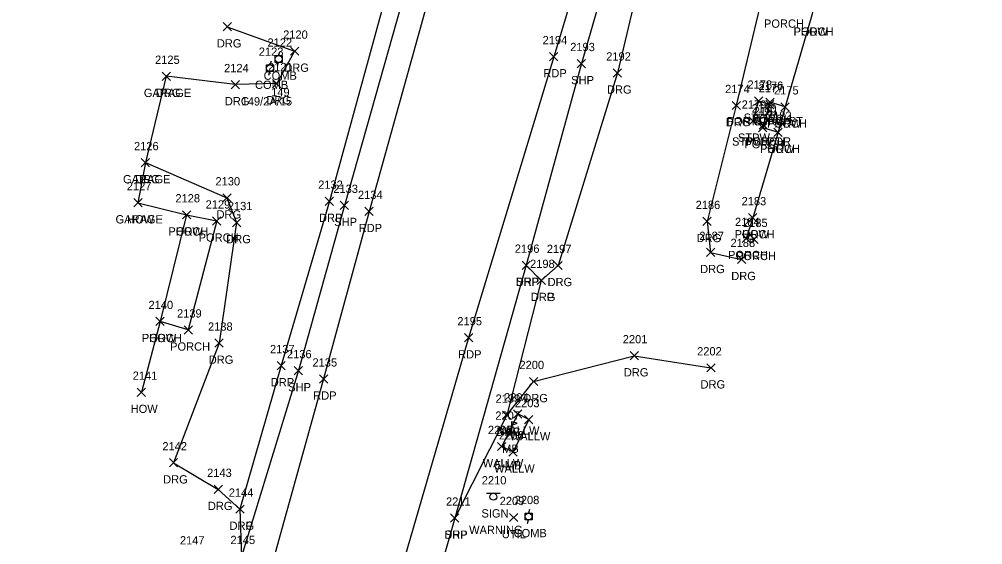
# Model space of a CAD drawing. Extents: x 1443071 to 1445292, y 614024 to 622563.
# Drawn here: x 1444521.8 to 1444754.4, y 622066 to 622193 of the extents above; entities that cross this region are included whole.
import ezdxf

# ---------------------------------------------------------------- set-up
doc = ezdxf.new("R2010")
doc.units = 0
for name, color, linetype in [('L_A', 7, 'Continuous'), ('L_C', 7, 'Continuous'), ('L_I', 7, 'Continuous'), ('L_TIC', 7, 'Continuous'), ('LBC', 7, 'Continuous'), ('LBF', 7, 'Continuous'), ('LMB', 7, 'Continuous'), ('LW', 7, 'Continuous'), ('P_A', 7, 'Continuous'), ('P_I', 7, 'Continuous'), ('P_TIC', 7, 'Continuous'), ('PET', 7, 'Continuous'), ('PSP', 7, 'Continuous'), ('R_A', 7, 'Continuous'), ('R_I', 7, 'Continuous'), ('R_TIC', 7, 'Continuous'), ('RDG', 7, 'Continuous'), ('RDP', 7, 'Continuous'), ('S_A', 7, 'Continuous'), ('S_C', 7, 'Continuous'), ('S_I', 7, 'Continuous'), ('SSGN', 7, 'Continuous'), ('U_A', 7, 'Continuous'), ('U_C', 7, 'Continuous'), ('U_I', 7, 'Continuous'), ('UDEFAULT', 7, 'Continuous'), ('UP', 7, 'Continuous')]:
    doc.layers.add(name, color=color, linetype=linetype)

msp = doc.modelspace()

# ---------------------------------------------------------------- linework, layer by layer
at = {"layer": 'L_TIC'}
for points in [[(1444556.27, 622178.18), (1444558.27, 622180.18)], [(1444558.27, 622178.18), (1444556.27, 622180.18)], [(1444699.32, 622172.18), (1444701.32, 622174.18)], [(1444701.32, 622172.18), (1444699.32, 622174.18)], [(1444702.03, 622171.33), (1444704.03, 622173.33)], [(1444704.03, 622171.33), (1444702.03, 622173.33)], [(1444702.03, 622171.33), (1444704.03, 622173.33)], [(1444704.03, 622171.33), (1444702.03, 622173.33)], [(1444702.04, 622171.91), (1444704.04, 622173.91)], [(1444704.04, 622171.91), (1444702.04, 622173.91)], [(1444705.72, 622170.79), (1444707.72, 622172.79)], [(1444707.72, 622170.79), (1444705.72, 622172.79)], [(1444705.72, 622170.79), (1444707.72, 622172.79)], [(1444707.72, 622170.79), (1444705.72, 622172.79)], [(1444697.93, 622167.36), (1444699.93, 622169.36)], [(1444699.93, 622167.36), (1444697.93, 622169.36)], [(1444700.27, 622165.77), (1444702.27, 622167.77)], [(1444702.27, 622165.77), (1444700.27, 622167.77)], [(1444700.44, 622166.43), (1444702.44, 622168.43)], [(1444702.44, 622166.43), (1444700.44, 622168.43)], [(1444700.44, 622166.43), (1444702.44, 622168.43)], [(1444702.44, 622166.43), (1444700.44, 622168.43)], [(1444704.02, 622164.67), (1444706.02, 622166.67)], [(1444706.02, 622164.67), (1444704.02, 622166.67)], [(1444704.02, 622164.67), (1444706.02, 622166.67)], [(1444706.02, 622164.67), (1444704.02, 622166.67)], [(1444551.25, 622157.32), (1444553.25, 622159.32)], [(1444553.25, 622157.32), (1444551.25, 622159.32)], [(1444549.44, 622147.62), (1444551.44, 622149.62)], [(1444551.44, 622147.62), (1444549.44, 622149.62)], [(1444549.44, 622147.62), (1444551.44, 622149.62)], [(1444551.44, 622147.62), (1444549.44, 622149.62)], [(1444561.18, 622144.71), (1444563.18, 622146.71)], [(1444563.18, 622144.71), (1444561.18, 622146.71)], [(1444561.18, 622144.71), (1444563.18, 622146.71)], [(1444563.18, 622144.71), (1444561.18, 622146.71)], [(1444568.49, 622143.22), (1444570.49, 622145.22)], [(1444570.49, 622143.22), (1444568.49, 622145.22)], [(1444697.9, 622144.01), (1444699.9, 622146.01)], [(1444699.9, 622144.01), (1444697.9, 622146.01)], [(1444697.9, 622144.01), (1444699.9, 622146.01)], [(1444699.9, 622144.01), (1444697.9, 622146.01)], [(1444696.31, 622139), (1444698.31, 622141)], [(1444698.31, 622139), (1444696.31, 622141)], [(1444698.24, 622138.77), (1444700.24, 622140.77)], [(1444700.24, 622138.77), (1444698.24, 622140.77)], [(1444554.78, 622118.94), (1444556.78, 622120.94)], [(1444556.78, 622118.94), (1444554.78, 622120.94)], [(1444554.78, 622118.94), (1444556.78, 622120.94)], [(1444556.78, 622118.94), (1444554.78, 622120.94)], [(1444561.59, 622116.89), (1444563.59, 622118.89)], [(1444563.59, 622116.89), (1444561.59, 622118.89)], [(1444550.3, 622101.84), (1444552.3, 622103.84)], [(1444552.3, 622101.84), (1444550.3, 622103.84)], [(1444641.17, 622096.61), (1444643.17, 622098.61)], [(1444643.17, 622096.61), (1444641.17, 622098.61)], [(1444643.8, 622095.22), (1444645.8, 622097.22)], [(1444645.8, 622095.22), (1444643.8, 622097.22)], [(1444643.8, 622095.22), (1444645.8, 622097.22)], [(1444645.8, 622095.22), (1444643.8, 622097.22)], [(1444637.28, 622088.73), (1444639.28, 622090.73)], [(1444639.28, 622088.73), (1444637.28, 622090.73)], [(1444640.02, 622087.42), (1444642.02, 622089.42)], [(1444642.02, 622087.42), (1444640.02, 622089.42)], [(1444640.02, 622087.42), (1444642.02, 622089.42)], [(1444642.02, 622087.42), (1444640.02, 622089.42)]]:
    msp.add_lwpolyline(points, dxfattribs=at)
at = {"layer": 'LBC'}
for points in [[(1444744.88, 622235.69), (1444725.69, 622241.03), (1444723.59, 622234.25), (1444722.14, 622228.45), (1444716.63, 622208.31), (1444713.14, 622193.99), (1444706.72, 622171.79), (1444705.02, 622165.67), (1444698.9, 622145.01)], [(1444557.27, 622179.18), (1444552.25, 622158.32), (1444550.44, 622148.62)], [(1444550.44, 622148.62), (1444562.18, 622145.71), (1444555.78, 622119.94), (1444551.3, 622102.84)]]:
    msp.add_lwpolyline(points, dxfattribs=at)
at = {"layer": 'LBF'}
for points in [[(1444703.03, 622172.33), (1444700.32, 622173.18), (1444698.93, 622168.36), (1444701.44, 622167.43)], [(1444706.72, 622171.79), (1444703.04, 622172.91), (1444703.03, 622172.33), (1444701.44, 622167.43), (1444701.27, 622166.77), (1444705.02, 622165.67)], [(1444562.18, 622145.71), (1444569.49, 622144.22), (1444562.59, 622117.89), (1444555.78, 622119.94)], [(1444698.9, 622145.01), (1444697.31, 622140), (1444699.24, 622139.77)]]:
    msp.add_lwpolyline(points, dxfattribs=at)
at = {"layer": 'LMB'}
for p, q in [((1444640.73, 622093.2), (1444640.73, 622095.8)), ((1444640.73, 622095.79), (1444642.02, 622095.41)), ((1444640.73, 622094.89), (1444642.02, 622095.4)), ((1444640.08, 622093.19), (1444640.08, 622093.19))]:
    msp.add_line(p, q, dxfattribs=at)
msp.add_circle((1444640.08, 622093.19), 0.656, dxfattribs=at)
at = {"layer": 'LW'}
for points in [[(1444644.8, 622096.22), (1444642.17, 622097.61), (1444638.28, 622089.73), (1444641.02, 622088.42)], [(1444644.8, 622096.22), (1444641.02, 622088.42)]]:
    msp.add_lwpolyline(points, dxfattribs=at)
at = {"layer": 'P_TIC'}
for points in [[(1444649.85, 622182.92), (1444651.85, 622184.92)], [(1444651.85, 622182.92), (1444649.85, 622184.92)], [(1444656.52, 622181.26), (1444658.52, 622183.26)], [(1444658.52, 622181.26), (1444656.52, 622183.26)], [(1444599.31, 622146.99), (1444601.31, 622148.99)], [(1444601.31, 622146.99), (1444599.31, 622148.99)], [(1444605.26, 622145.53), (1444607.26, 622147.53)], [(1444607.26, 622145.53), (1444605.26, 622147.53)], [(1444643.19, 622132.53), (1444645.19, 622134.53)], [(1444645.19, 622132.53), (1444643.19, 622134.53)], [(1444629.28, 622115), (1444631.28, 622117)], [(1444631.28, 622115), (1444629.28, 622117)], [(1444588.19, 622107.06), (1444590.19, 622109.06)], [(1444590.19, 622107.06), (1444588.19, 622109.06)], [(1444594.29, 622105.04), (1444596.29, 622107.04)], [(1444596.29, 622105.04), (1444594.29, 622107.04)], [(1444625.95, 622071.43), (1444627.95, 622073.43)], [(1444627.95, 622071.43), (1444625.95, 622073.43)]]:
    msp.add_lwpolyline(points, dxfattribs=at)
at = {"layer": 'PET'}
for points in [[(1444754.44, 622544.13), (1444741.07, 622497.37), (1444724.21, 622436.63), (1444710.62, 622388.87), (1444697.45, 622342.15), (1444675, 622264.13), (1444650.85, 622183.92), (1444630.28, 622116), (1444610.88, 622049.25), (1444594.96, 621996.24), (1444563.37, 621884.27), (1444533.4, 621779.05), (1444495.09, 621640.86), (1444437.04, 621433.18), (1444409.83, 621332.84), (1444393.99, 621275.61), (1444360.23, 621155.32)], [(1444707.59, 622509.11), (1444700.19, 622484.07), (1444679.05, 622409.28), (1444655.77, 622327.83), (1444650.07, 622306.66), (1444636.13, 622255.68), (1444623.55, 622208.8), (1444606.26, 622146.53), (1444595.29, 622106.04), (1444582.56, 622060.23), (1444534.43, 621893.79), (1444481.57, 621704.27), (1444439.29, 621553.82), (1444408.11, 621445.28), (1444395.03, 621397.39), (1444367.96, 621301.44), (1444350.41, 621238.76), (1444319.14, 621126.97)]]:
    msp.add_lwpolyline(points, dxfattribs=at)
at = {"layer": 'PSP'}
for points in [[(1444703.05, 622509.58), (1444696.35, 622485.04), (1444679.96, 622426.95), (1444670.67, 622398.4), (1444651.65, 622328.99), (1444645.77, 622309.01), (1444600.31, 622147.99), (1444589.19, 622108.06), (1444575.49, 622063.15), (1444529.28, 621895.39), (1444476.53, 621706.36), (1444455.46, 621630.82), (1444442.09, 621578.45), (1444424.77, 621519.75), (1444412.09, 621475.26), (1444390.88, 621397.93), (1444363.76, 621301.82), (1444345.99, 621239.2), (1444324.65, 621163.68)], [(1444745.15, 622495.54), (1444738.65, 622472.69), (1444728.21, 622436.2), (1444714.89, 622387.13), (1444701.45, 622339.69), (1444679.77, 622260.17), (1444671.12, 622229.57), (1444657.52, 622182.26), (1444644.19, 622133.53), (1444626.95, 622072.43), (1444608.5, 622007.83), (1444599.1, 621977.5), (1444572.99, 621881.76), (1444551.74, 621805.05), (1444541.41, 621769.53), (1444519.46, 621688.51), (1444505.68, 621638.77), (1444452.32, 621450.13), (1444441.68, 621411.27), (1444418.22, 621330.76), (1444405.98, 621283.95), (1444397.04, 621252.99), (1444383.69, 621203.04)]]:
    msp.add_lwpolyline(points, dxfattribs=at)
at = {"layer": 'R_TIC'}
for points in [[(1444571.01, 622190.14), (1444573.01, 622192.14)], [(1444573.01, 622190.14), (1444571.01, 622192.14)], [(1444587.29, 622184.26), (1444589.29, 622186.26)], [(1444589.29, 622184.26), (1444587.29, 622186.26)], [(1444556.27, 622178.18), (1444558.27, 622180.18)], [(1444558.27, 622178.18), (1444556.27, 622180.18)], [(1444665.21, 622178.99), (1444667.21, 622180.99)], [(1444667.21, 622178.99), (1444665.21, 622180.99)], [(1444572.95, 622176.17), (1444574.95, 622178.17)], [(1444574.95, 622176.17), (1444572.95, 622178.17)], [(1444582.97, 622176.42), (1444584.97, 622178.42)], [(1444584.97, 622176.42), (1444582.97, 622178.42)], [(1444693.93, 622171.12), (1444695.93, 622173.12)], [(1444695.93, 622171.12), (1444693.93, 622173.12)], [(1444551.25, 622157.32), (1444553.25, 622159.32)], [(1444553.25, 622157.32), (1444551.25, 622159.32)], [(1444570.94, 622148.81), (1444572.94, 622150.81)], [(1444572.94, 622148.81), (1444570.94, 622150.81)], [(1444595.67, 622147.99), (1444597.67, 622149.99)], [(1444597.67, 622147.99), (1444595.67, 622149.99)], [(1444573.28, 622142.84), (1444575.28, 622144.84)], [(1444575.28, 622142.84), (1444573.28, 622144.84)], [(1444686.86, 622143.11), (1444688.86, 622145.11)], [(1444688.86, 622143.11), (1444686.86, 622145.11)], [(1444687.71, 622135.62), (1444689.71, 622137.62)], [(1444689.71, 622135.62), (1444687.71, 622137.62)], [(1444695.22, 622133.93), (1444697.22, 622135.93)], [(1444697.22, 622133.93), (1444695.22, 622135.93)], [(1444643.19, 622132.53), (1444645.19, 622134.53)], [(1444645.19, 622132.53), (1444643.19, 622134.53)], [(1444650.88, 622132.47), (1444652.88, 622134.47)], [(1444652.88, 622132.47), (1444650.88, 622134.47)], [(1444646.82, 622128.87), (1444648.82, 622130.87)], [(1444648.82, 622128.87), (1444646.82, 622130.87)], [(1444646.82, 622128.87), (1444648.82, 622130.87)], [(1444648.82, 622128.87), (1444646.82, 622130.87)], [(1444569.05, 622113.71), (1444571.05, 622115.71)], [(1444571.05, 622113.71), (1444569.05, 622115.71)], [(1444669.29, 622110.66), (1444671.29, 622112.66)], [(1444671.29, 622110.66), (1444669.29, 622112.66)], [(1444584.03, 622108.27), (1444586.03, 622110.27)], [(1444586.03, 622108.27), (1444584.03, 622110.27)], [(1444687.81, 622107.74), (1444689.81, 622109.74)], [(1444689.81, 622107.74), (1444687.81, 622109.74)], [(1444645, 622104.43), (1444647, 622106.43)], [(1444647, 622104.43), (1444645, 622106.43)], [(1444638.5, 622096.3), (1444640.5, 622098.3)], [(1444640.5, 622096.3), (1444638.5, 622098.3)], [(1444638.5, 622096.3), (1444640.5, 622098.3)], [(1444640.5, 622096.3), (1444638.5, 622098.3)], [(1444558.04, 622084.79), (1444560.04, 622086.79)], [(1444560.04, 622084.79), (1444558.04, 622086.79)], [(1444568.84, 622078.37), (1444570.84, 622080.37)], [(1444570.84, 622078.37), (1444568.84, 622080.37)], [(1444574.08, 622073.59), (1444576.08, 622075.59)], [(1444576.08, 622073.59), (1444574.08, 622075.59)], [(1444574.08, 622073.59), (1444576.08, 622075.59)], [(1444576.08, 622073.59), (1444574.08, 622075.59)], [(1444625.95, 622071.43), (1444627.95, 622073.43)], [(1444627.95, 622071.43), (1444625.95, 622073.43)]]:
    msp.add_lwpolyline(points, dxfattribs=at)
at = {"layer": 'RDG'}
for points in [[(1444683.02, 622255.19), (1444696.87, 622250.43), (1444712.88, 622241.02), (1444711.87, 622227.43), (1444702.35, 622203.55), (1444694.93, 622172.12), (1444687.86, 622144.11), (1444688.71, 622136.62), (1444696.22, 622134.93)], [(1444674.55, 622230.15), (1444676.7, 622224.22), (1444666.21, 622179.99), (1444651.88, 622133.47), (1444647.82, 622129.87)], [(1444572.01, 622191.14), (1444588.29, 622185.26), (1444583.97, 622177.42), (1444573.95, 622177.17), (1444557.27, 622179.18)], [(1444552.25, 622158.32), (1444571.94, 622149.81), (1444574.28, 622143.84), (1444570.05, 622114.71), (1444559.04, 622085.79), (1444569.84, 622079.37), (1444575.08, 622074.59)], [(1444639.5, 622097.3), (1444646, 622105.43), (1444670.29, 622111.66), (1444688.81, 622108.74)]]:
    msp.add_lwpolyline(points, dxfattribs=at)
at = {"layer": 'RDP'}
for points in [[(1444645.77, 622309.01), (1444638.9, 622301.63), (1444626.44, 622256.61), (1444620.83, 622237.39), (1444614.71, 622214.93), (1444596.67, 622148.99), (1444585.03, 622109.27), (1444575.08, 622074.59), (1444575.49, 622063.15)], [(1444644.19, 622133.53), (1444647.82, 622129.87), (1444639.5, 622097.3), (1444626.95, 622072.43)]]:
    msp.add_lwpolyline(points, dxfattribs=at)
at = {"layer": 'SSGN'}
for p, q in [((1444634.62, 622078.43), (1444637.95, 622078.43)), ((1444636.27, 622077.59), (1444636.27, 622077.59))]:
    msp.add_line(p, q, dxfattribs=at)
msp.add_circle((1444636.27, 622077.59), 0.833, dxfattribs=at)
at = {"layer": 'UDEFAULT'}
for points in [[(1444640.15, 622071.57), (1444642.15, 622073.57)], [(1444642.15, 622071.57), (1444640.15, 622073.57)]]:
    msp.add_lwpolyline(points, dxfattribs=at)
at = {"layer": 'UP'}
for p, q in [((1444583.58, 622182.5), (1444583.58, 622184.17)), ((1444583.58, 622184.17), (1444585.24, 622184.17)), ((1444584.66, 622185), (1444584.41, 622184.17)), ((1444585.24, 622184.17), (1444585.24, 622182.5)), ((1444581.49, 622180.3), (1444581.49, 622181.96)), ((1444581.49, 622181.96), (1444583.16, 622181.96)), ((1444582.58, 622182.8), (1444582.33, 622181.96)), ((1444583.16, 622181.96), (1444583.16, 622180.3)), ((1444585.24, 622182.5), (1444583.58, 622182.5)), ((1444584.16, 622181.67), (1444584.41, 622182.5)), ((1444584.41, 622183.34), (1444584.41, 622183.34)), ((1444583.16, 622180.3), (1444581.49, 622180.3)), ((1444582.08, 622179.46), (1444582.33, 622180.3)), ((1444582.33, 622181.13), (1444582.33, 622181.13)), ((1444645.01, 622074.48), (1444644.76, 622073.65)), ((1444643.93, 622071.98), (1444643.93, 622073.65)), ((1444643.93, 622073.65), (1444645.6, 622073.65)), ((1444644.76, 622072.81), (1444644.76, 622072.81)), ((1444645.6, 622073.65), (1444645.6, 622071.98)), ((1444645.6, 622071.98), (1444643.93, 622071.98)), ((1444644.51, 622071.15), (1444644.76, 622071.98))]:
    msp.add_line(p, q, dxfattribs=at)
for centre in [(1444584.41, 622183.34), (1444582.33, 622181.13), (1444644.76, 622072.81)]:
    msp.add_circle(centre, 0.833, dxfattribs=at)

# ---------------------------------------------------------------- texts
at = {"layer": 'L_A'}
for s, p in [('PORCH', (1444701.61, 622190.91)), ('PORCH', (1444708.76, 622188.99)), ('HOW', (1444710.52, 622188.99)), ('GARAGE', (1444551.87, 622174.18)), ('STPW', (1444696.71, 622168.18)), ('PORCH', (1444698.66, 622167.91)), ('POR STPW ST', (1444692.61, 622167.33)), ('PORCH', (1444698.65, 622167.33)), ('PORCH', (1444702.34, 622166.79)), ('HOW', (1444704.11, 622166.79)), ('STPW', (1444695.32, 622163.36)), ('STPW POR', (1444693.89, 622162.43)), ('PORCH', (1444696.89, 622161.77)), ('PORCH', (1444697.06, 622162.43)), ('PORCH', (1444700.64, 622160.67)), ('HOW', (1444702.41, 622160.67)), ('GARAGE', (1444546.85, 622153.32)), ('GARAGE', (1444545.04, 622143.62)), ('HOW', (1444547.83, 622143.62)), ('PORCH', (1444557.8, 622140.71)), ('HOW', (1444559.57, 622140.71)), ('PORCH', (1444694.52, 622140.01)), ('HOW', (1444696.29, 622140.01)), ('PORCH', (1444565.11, 622139.22)), ('PORCH', (1444692.93, 622135)), ('PORCH', (1444694.86, 622134.77)), ('PORCH', (1444551.4, 622114.94)), ('HOW', (1444553.16, 622114.94)), ('PORCH', (1444558.21, 622112.89)), ('HOW', (1444548.69, 622097.84)), ('WALLW', (1444637.59, 622092.61)), ('WALLW', (1444640.22, 622091.22)), ('WALLW', (1444640.22, 622091.22)), ('MB', (1444638.39, 622088.19)), ('WALLW', (1444633.7, 622084.73)), ('WALLW', (1444636.44, 622083.42)), ('WALLW', (1444636.44, 622083.42))]:
    msp.add_text(s, height=2, dxfattribs=at).set_placement(p)
at = {"layer": 'L_C'}
msp.add_text('5-MB', height=2, dxfattribs=at).set_placement((1444636.67, 622084.19))
at = {"layer": 'L_I'}
for s, p in [('2125', (1444554.58, 622182.18)), ('2178', (1444697.62, 622176.18)), ('2176', (1444700.29, 622175.91)), ('2177', (1444700.34, 622175.33)), ('2177', (1444700.34, 622175.33)), ('2175', (1444704.03, 622174.79)), ('2175', (1444704.03, 622174.79)), ('2179', (1444696.23, 622171.36)), ('2180', (1444698.66, 622170.43)), ('2180', (1444698.66, 622170.43)), ('2181', (1444699.14, 622169.77)), ('2182', (1444702.33, 622168.67)), ('2182', (1444702.33, 622168.67)), ('2126', (1444549.5, 622161.32)), ('2127', (1444547.75, 622151.62)), ('2127', (1444547.75, 622151.62)), ('2128', (1444559.49, 622148.71)), ('2128', (1444559.49, 622148.71)), ('2129', (1444566.79, 622147.22)), ('2183', (1444696.21, 622148.01)), ('2183', (1444696.21, 622148.01)), ('2184', (1444694.62, 622143)), ('2185', (1444696.55, 622142.77)), ('2140', (1444553, 622122.94)), ('2140', (1444553, 622122.94)), ('2139', (1444559.89, 622120.89)), ('2141', (1444549.18, 622105.84)), ('2204', (1444638.83, 622100.61)), ('2203', (1444641.47, 622099.22)), ('2203', (1444641.47, 622099.22)), ('2207', (1444636.74, 622096.19)), ('2205', (1444634.95, 622092.73)), ('2206', (1444637.63, 622091.42)), ('2206', (1444637.63, 622091.42)), ('2147', (1444560.58, 622066.06))]:
    msp.add_text(s, height=2, dxfattribs=at).set_placement(p)
at = {"layer": 'P_A'}
for s, p in [('RDP', (1444648.34, 622178.92)), ('SHP', (1444655.06, 622177.26)), ('SHP', (1444597.85, 622142.99)), ('RDP', (1444603.75, 622141.53)), ('SHP', (1444641.73, 622128.53)), ('RDP', (1444627.76, 622111)), ('SHP', (1444586.73, 622103.06)), ('RDP', (1444592.77, 622101.04)), ('SHP', (1444624.49, 622067.43))]:
    msp.add_text(s, height=2, dxfattribs=at).set_placement(p)
at = {"layer": 'P_I'}
for s, p in [('2194', (1444648.16, 622186.92)), ('2193', (1444654.83, 622185.26)), ('2133', (1444597.62, 622150.99)), ('2134', (1444603.57, 622149.53)), ('2196', (1444641.45, 622136.53)), ('2195', (1444627.58, 622119)), ('2136', (1444586.44, 622111.06)), ('2135', (1444592.59, 622109.04)), ('2211', (1444624.83, 622075.43)), ('2145', (1444572.79, 622066.15))]:
    msp.add_text(s, height=2, dxfattribs=at).set_placement(p)
at = {"layer": 'R_A'}
for s, p in [('DRG', (1444569.5, 622186.14)), ('DRG', (1444585.78, 622180.26)), ('DRG', (1444663.7, 622174.99)), ('DRG', (1444554.76, 622174.18)), ('DRG', (1444581.46, 622172.42)), ('DRG', (1444571.43, 622172.17)), ('DRG', (1444692.41, 622167.12)), ('DRG', (1444549.74, 622153.32)), ('DRG', (1444569.43, 622144.81)), ('DRP', (1444594.16, 622143.99)), ('DRG', (1444571.77, 622138.84)), ('DRG', (1444685.35, 622139.11)), ('DRG', (1444686.19, 622131.62)), ('DRP', (1444641.68, 622128.53)), ('DRG', (1444649.36, 622128.47)), ('DRG', (1444693.71, 622129.93)), ('DRG', (1444645.31, 622124.87)), ('DRP', (1444645.31, 622124.87)), ('DRG', (1444567.54, 622109.71)), ('DRG', (1444667.77, 622106.66)), ('DRP', (1444582.52, 622104.27)), ('DRG', (1444686.3, 622103.74)), ('DRG', (1444643.49, 622100.43)), ('DRG', (1444636.99, 622092.3)), ('DRP', (1444636.99, 622092.3)), ('DRG', (1444556.53, 622080.79)), ('DRG', (1444567.33, 622074.37)), ('DRG', (1444572.56, 622069.59)), ('DRP', (1444572.56, 622069.59)), ('DRP', (1444624.44, 622067.43))]:
    msp.add_text(s, height=2, dxfattribs=at).set_placement(p)
at = {"layer": 'R_I'}
for s, p in [('2120', (1444585.51, 622188.26)), ('2125', (1444554.58, 622182.18)), ('2192', (1444663.52, 622182.99)), ('2124', (1444571.25, 622180.17)), ('2121', (1444581.84, 622180.42)), ('2174', (1444692.23, 622175.12)), ('2126', (1444549.5, 622161.32)), ('2130', (1444569.17, 622152.81)), ('2132', (1444593.97, 622151.99)), ('2131', (1444572.15, 622146.84)), ('2186', (1444685.11, 622147.11)), ('2187', (1444686.01, 622139.62)), ('2188', (1444693.53, 622137.93)), ('2196', (1444641.45, 622136.53)), ('2197', (1444649.18, 622136.47)), ('2198', (1444645.13, 622132.87)), ('2198', (1444645.13, 622132.87)), ('2138', (1444567.36, 622117.71)), ('2201', (1444667.51, 622114.66)), ('2137', (1444582.34, 622112.27)), ('2202', (1444685.47, 622111.74)), ('2200', (1444642.57, 622108.43)), ('2199', (1444636.8, 622100.3)), ('2199', (1444636.8, 622100.3)), ('2142', (1444556.35, 622088.79)), ('2143', (1444567.15, 622082.37)), ('2144', (1444572.38, 622077.59)), ('2144', (1444572.38, 622077.59)), ('2211', (1444624.83, 622075.43)), ('2145', (1444572.79, 622066.15))]:
    msp.add_text(s, height=2, dxfattribs=at).set_placement(p)
at = {"layer": 'S_A'}
msp.add_text('SIGN', height=2, dxfattribs=at).set_placement((1444633.4, 622072.57))
at = {"layer": 'S_C'}
msp.add_text('WARNING', height=2, dxfattribs=at).set_placement((1444630.41, 622068.57))
at = {"layer": 'S_I'}
msp.add_text('2210', height=2, dxfattribs=at).set_placement((1444633.47, 622080.57))
at = {"layer": 'U_A'}
for s, p in [('COMB', (1444580.8, 622178.34)), ('COMB', (1444578.71, 622176.13)), ('COMB', (1444641.15, 622067.81)), ('UTIL', (1444638.31, 622067.57))]:
    msp.add_text(s, height=2, dxfattribs=at).set_placement(p)
at = {"layer": 'U_C'}
for s, p in [('149', (1444582.61, 622174.34)), ('149/2A/15', (1444575.48, 622172.13))]:
    msp.add_text(s, height=2, dxfattribs=at).set_placement(p)
at = {"layer": 'U_I'}
for s, p in [('2122', (1444581.72, 622186.34)), ('2123', (1444579.63, 622184.13)), ('2209', (1444637.8, 622075.57)), ('2208', (1444641.42, 622075.81))]:
    msp.add_text(s, height=2, dxfattribs=at).set_placement(p)

doc.saveas('drawing.dxf')
